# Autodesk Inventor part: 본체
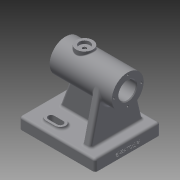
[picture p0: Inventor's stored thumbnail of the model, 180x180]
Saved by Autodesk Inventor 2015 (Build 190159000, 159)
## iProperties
Created: 2022-06
Part Number: 본체
Material: 일반
Document SubType Name: Modeling
Designer: 10401
Density: 1 g/cm^3
Appearance: 기본값
Author: 10401
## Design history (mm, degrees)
sketch "스케치1"
  geometry: C1 r 21 at (0, 0); 1 further point
  constraints: 1 centre point, 1 coincident
  dimensions: "d0" = 42 diameter of C1
extrude "돌출1" new body sketch "스케치1" stored distance "d1" = 82; taper "d2" = 0 deg
sketch "스케치2"
  geometry: L1 (41, 21)-(41, -21) reference; L2 (41, -21)-(-41, -21) reference; L3 (-41, -21)-(-41, 21) reference; L4 (-41, 21)-(41, 21) reference; L5 (41, 0)-(-41, 0); L6 (41, 14.5)-(-21, 14.5); L7 (-21, 14.5)-(-21, 11.5); L8 (-21, 11.5)-(-41, 11.5); 1 further point
  constraints: 8 end point, 2 horizontal, 2 midpoint, 2 point on line, 1 perpendicular
  dimensions: "d3" = 62 distance of L6.start L6.end; "d4" = 29 diameter of L6 L5; "d5" = 23 diameter of L8 L5
revolve "회전1" sketch "스케치2" stored, may be unused: angle "d6" = 90 deg
node "작업 평면2"
sketch "스케치4"
  geometry: L1 (-59, 43)-(41, 43); L2 (41, 43)-(41, -43); L3 (41, -43)-(-59, -43); L4 (-59, -43)-(-59, 43); L5 (41, -21)-(41, 21) reference; L6 (-59, 0)-(41, 0); 1 further point
  constraints: 10 end point, 2 midpoint, 2 parallel, 1 collinear, 1 horizontal, 1 perpendicular, 1 other
  dimensions: "d12" = 86 distance of L1.end L2.end; "d13" = 100 distance of L1.start L1.end
extrude "돌출2" join sketch "스케치4" distance "d14" = 15; taper "d15" = 0 deg
sketch "스케치5"
  geometry: L1 (41, 43)-(-59, 43) reference; L2 (-59, 43)-(-59, -43) reference; L3 (41, -43)-(41, 43) reference; L4 (-44, 5)-(26, 5); L5 (26, 5)-(26, -5); L6 (26, -5)-(-44, -5); L7 (-44, -5)-(-44, 5); L8 (16, 35)-(26, 35); L9 (26, 35)-(26, -35); L10 (26, -35)-(16, -35); L11 (16, -35)-(16, 35); L12 (16, 35)-(26, -35); L13 (26, 35)-(16, -35); L14 (-59, -43)-(41, -43) reference; 4 further points
  constraints: 20 end point, 4 parallel, 3 midpoint, 2 horizontal, 2 perpendicular, 1 collinear, 1 horizontal alignment
  dimensions: "d16" = 10 distance between parallel lines of L9 L11; "d17" = 10 distance of L6.end L4.start; "d18" = 15 distance between parallel lines of L3 L9; "d20" = 15 distance between parallel lines of L2 L7; "d139" = 5 distance from line of L6 point (0, 0); "d140" = 8 distance between parallel lines of L14 L10; "d141" = 8 distance between parallel lines of L1 L8
extrude "돌출3" join sketch "스케치5" distance "d21" = 57; taper "d22" = 0 deg
feature "면 기울기1" dims angle "d23" = 20 deg
node "작업 평면3"
sketch "스케치6"
  geometry: L1 (-15, 86)-(0, 86) reference; L2 (0, 86)-(0, 0) reference; L3 (0, 0)-(-15, 0) reference; L4 (-15, 0)-(-15, 38) reference; L5 (-15, 48)-(-15, 86) reference; L6 (-76.814, 22.559)-(-15, 8); L7 (-76.814, 63.441)-(-15, 78); L8 (-72, 48)-(-61.644, 48) reference; L9 (-61.644, 38)-(-72, 38) reference; L10 (-72, 38)-(-72, 48) reference; L11 (-15, 38)-(-15, 48) reference; L12 (-15, 38)-(-51.604, 38) reference; L13 (-51.604, 48)-(-15, 48) reference; A1 r 11.5 centre (-72, 43) between (-61.644, 48) and (-61.644, 38) reference; A2 r 21 centre (-72, 43) between (-51.604, 48) and (-51.604, 38) reference; A3 r 11.5 centre (-72, 43) between (-61.644, 38) and (-61.644, 48) reference; A4 r 21 centre (-72, 43) between (-51.604, 38) and (-51.604, 48) reference; 1 further point
  constraints: 4 end point, 2 point on circle, 2 point on line, 2 tangent
  dimensions: "d25" = 8 distance from line of L7.end L1; "d26" = 8 distance from line of L6.end L3
extrude "돌출4" join sketch "스케치6" distance "d27" = 10; taper "d28" = 0 deg
sketch "스케치7"
  geometry: C1 r 12.5 at (0, 0) reference
extrude "돌출5" cut sketch "스케치7" stored distance "d29" = 10; taper "d30" = 0 deg
sketch "스케치9"
  geometry: C1 r 15.5 at (0, 0) reference; C2 r 21 at (0, 0) reference; C3 r 11.5 at (0, 0)
  constraints: 1 centre point, 1 coincident
  dimensions: "d34" = 23 diameter of C3
extrude "돌출7" join sketch "스케치9" distance "d35" = 20; taper "d36" = 0 deg
sketch "스케치10"
  geometry: L1 (41, 43)-(-59, 43) reference; L2 (-59, 43)-(-59, -43) reference; L3 (-37, 27)-(-17, 27); L4 (-33, 23)-(-21, 23); L5 (-21, 31)-(-33, 31); L6 (-37, -27)-(-17, -27); L7 (-33, -31)-(-21, -31); L8 (-21, -23)-(-33, -23); L9 (-21, 33)-(-33, 33); L10 (-33, 21)-(-21, 21); L11 (-21, -33)-(-33, -33); L12 (-33, -21)-(-21, -21); A1 r 4 centre (-33, 27) between (-33, 31) and (-33, 23); A2 r 4 centre (-21, 27) between (-21, 23) and (-21, 31); A3 r 4 centre (-33, -27) between (-33, -23) and (-33, -31); A4 r 4 centre (-21, -27) between (-21, -31) and (-21, -23); A5 r 6 centre (-33, 27) between (-33, 33) and (-33, 21); A6 r 6 centre (-21, 27) between (-21, 21) and (-21, 33); A7 r 6 centre (-33, -27) between (-33, -21) and (-33, -33); A8 r 6 centre (-21, -27) between (-21, -33) and (-21, -21); 3 further points
  constraints: 24 end point, 20 point on circle, 8 centre point, 8 tangent, 6 parallel, 4 point on line, 2 midpoint, 1 horizontal, 6 other
  dimensions: "d37" = 12 distance of L5.start L5.end; "d38" = 26 distance from line of L2 A1.centre; "d40" = 16 distance from line of point (-27, 27) L1; "d41" = 26 distance from line of L2 A3.centre; "d43" = 8 distance between parallel lines of L4 L5; "d44" = 8 distance between parallel lines of L7 L8; "d47" = 54 distance of point (-27, -27) point (-27, 27); "d79" = 2 radial gap between concentric circles of A2 A6; "d80" = 2 distance between parallel lines of L7 L11
extrude "돌출8" cut sketch "스케치10" stored distance "d48" = 20; taper "d49" = 0 deg
sketch "스케치11"
  geometry: C1 r 11.5 at (0, 0) reference; 1 further point
  dimensions: "d50" = 18 distance of C1.centre point (-18, 0)
hole "구멍1" sketch "스케치11" at (-18, 0) diameter "d51" = 2.459; stored, may be unused: countersink angle "d55" = 90 deg, drill point angle "d57" = 118 deg; dims "d52" = 8, "d53" = 4, "d54" = 2, "d56" = 10
sketch "스케치13"
  geometry: C1 r 11.5 at (0, 0) reference; C2 r 14.5 at (0, 0) reference
extrude "돌출10" cut sketch "스케치13" stored distance "d60" = 20; taper "d61" = 0 deg
sketch "스케치14"
  geometry: C1 r 14.5 at (0, 0) reference; 1 further point
  constraints: 1 horizontal alignment
  dimensions: "d65" = 18 distance of C1.centre point (18, 0)
hole "구멍2" sketch "스케치14" at (18, 0) diameter "d66" = 2.459; stored, may be unused: countersink angle "d70" = 90 deg, drill point angle "d72" = 118 deg; dims "d67" = 8, "d68" = 4, "d69" = 2, "d71" = 10
chamfer "모따기2" distance "d76" = 1; stored, may be unused: second distance "d77" = 2, angle "d78" = 45 deg
sketch "스케치16"
  geometry: L1 (-21, 23)-(-33, 23) reference; L2 (-33, 31)-(-21, 31) reference; L3 (-21, -31)-(-33, -31) reference; L4 (-33, -23)-(-21, -23) reference; L5 (-21, 20)-(-33, 20); L6 (-33, 34)-(-21, 34); L7 (-21, -34)-(-33, -34); L8 (-33, -20)-(-21, -20); A1 r 4 centre (-21, 27) between (-21, 23) and (-21, 31) reference; A2 r 4 centre (-33, 27) between (-33, 31) and (-33, 23) reference; A3 r 4 centre (-21, -27) between (-21, -31) and (-21, -23) reference; A4 r 4 centre (-33, -27) between (-33, -23) and (-33, -31) reference; A5 r 7 centre (-21, 27) between (-21, 20) and (-21, 34); A6 r 7 centre (-33, 27) between (-33, 34) and (-33, 20); A7 r 7 centre (-21, -27) between (-21, -34) and (-21, -20); A8 r 7 centre (-33, -27) between (-33, -20) and (-33, -34); 1 further point
  constraints: 8 end point, 8 point on circle, 4 centre point, 6 other
  dimensions: "d81" = 3 radial gap between concentric circles of A1 A5; "d82" = 3 radial gap between concentric circles of A3 A7
node "작업 평면4"
sketch "스케치17"
  geometry: L1 (41, -21)-(41, 21) reference; L2 (-41, 21)-(-41, -21) reference; C1 r 11 at (-16, 0); 1 further point
  constraints: 1 centre point, 1 horizontal alignment
  dimensions: "d114" = 22 diameter of C1; "d126" = 25 distance from line of L2 C1.centre
extrude "돌출12" join sketch "스케치17" stored distance "d87" = 3; taper "d88" = 0 deg
fillet "모깎기3" dims "d101" = 3
fillet "모깎기4" dims "d102" = 3
fillet "모깎기5" dims "d103" = 3
fillet "모깎기6" dims "d104" = 3
extrude "돌출14" join sketch "스케치16" distance "d105" = 3; taper "d106" = 0 deg
fillet "모깎기7" dims "d107" = 3
fillet "모깎기8" dims "d108" = 3
sketch "스케치20"
  geometry: L1 (0, 80)-(0, 0) reference; 2 further points
  constraints: 1 horizontal alignment, 1 other
  dimensions: "d109" = 6 distance from line of L1 point (-6, 40)
feature "엠보싱2" sketch "스케치20" dims "d0" = 42, "d112" = 0.5, "d113" = 0
sketch "스케치22"
  geometry: C1 r 11 at (0, 0) reference; C2 r 7 at (0, 0); 1 further point
  constraints: 1 centre point, 1 coincident
  dimensions: "d127" = 14 diameter of C2
extrude "돌출16" cut sketch "스케치22" distance "d128" = 4; taper "d129" = 0 deg
sketch "스케치23"
  geometry: C1 r 7 at (0, 0) reference; 1 further point
hole "구멍5" sketch "스케치23" at (0, 0) diameter "d130" = 4.917; stored, may be unused: countersink angle "d134" = 90 deg, drill point angle "d136" = 0 deg; dims "d131" = 12, "d132" = 4, "d133" = 2, "d135" = 24
fillet "모깎기9" dims "d142" = 1
node "솔리드1"
pattern_circular "원형 패턴1" dims angle "d63" = 360 deg
pattern_circular "원형 패턴2" dims angle "d74" = 360 deg
node "절단 모서리 투영1"
node "절단 모서리 투영2"
other parameters: "d11" = -72, "d24" = -15, "d85" = 24
